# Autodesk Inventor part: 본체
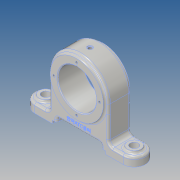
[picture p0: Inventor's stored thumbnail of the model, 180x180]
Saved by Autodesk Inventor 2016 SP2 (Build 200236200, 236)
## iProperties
Created: 2019-05
Part Number: 본체
Material: 알루미늄 6061
Document SubType Name: Modeling
Designer: EZ
Density: 2.7 g/cm^3
Appearance: 알루미늄 - 평지
Mass: 456.014 g
Surface Area: 318.8 cm^2
Volume: 168.894 cm^3
Author: EZ
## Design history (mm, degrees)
sketch "스케치1"
  geometry: L1 (-60, 0)-(60, 0); L2 (-60, -15)-(60, -15); L3 (60, 15)-(-60, 15); A1 r 15 centre (-60, 0) between (-60, 15) and (-60, -15); A2 r 15 centre (60, 0) between (60, -15) and (60, 15); 2 further points
  constraints: 8 end point, 4 point on circle, 4 tangent, 2 centre point, 1 coincident, 1 horizontal, 1 midpoint, 1 parallel
  dimensions: "d0" = 150 dimension on A2 A1; "d1" = 120 distance of L3.start L3.end
extrude "돌출1" new body sketch "스케치1" distance "d2" = 12; taper "d3" = 0 deg
sketch "스케치2"
  geometry: L1 (0, 0)-(0, 60); L2 (0, 0)-(0, 100); L3 (-40, 60)-(-40, 0); L4 (40, 60)-(40, 0); L5 (-40, 0)-(40, 0); L6 (60, 0)-(-60, 0) reference; A1 r 40 centre (0, 60) between (0, 100) and (-40, 60)
  constraints: 10 end point, 4 vertical, 3 point on circle, 1 centre point, 1 coincident, 1 collinear, 1 tangent
  dimensions: "d4" = 60 distance of L1.start L1.end; "d6" = 100 distance of L1.start L2.end
extrude "돌출2" join sketch "스케치2" stored distance "d7" = 30; taper "d8" = 0 deg
sketch "스케치3"
  geometry: L1 (-60, 0)-(60, 0) reference; C1 r 36 at (0, 60); 1 further point
  constraints: 1 centre point
  dimensions: "d9" = 72 diameter of C1; "d10" = 60 distance from line of L1 C1.centre
extrude "돌출3" join sketch "스케치3" stored distance "d11" = 36; taper "d12" = 0 deg
sketch "스케치4"
  geometry: C1 r 36 at (0, 0) reference; C2 r 26 at (0, 0); 1 further point
  constraints: 1 centre point, 1 coincident
  dimensions: "d13" = 52 diameter of C2
extrude "돌출4" cut sketch "스케치4" stored distance "d14" = 36; taper "d15" = 0 deg
sketch "스케치5" dims "d16" = 62
  geometry: L1 (0, 0)-(0, 31); C1 r 36 at (0, 0) reference; 1 further point
  constraints: 2 end point, 1 coincident, 1 vertical, 1 vertical alignment, 2 other
hole "구멍1" sketch "스케치5" at (0, 31) diameter "d17" = 3.242; stored, may be unused: countersink angle "d21" = 90 deg, drill point angle "d23" = 118 deg; dims "d18" = 6, "d19" = 4, "d20" = 2, "d22" = 8
sketch "스케치6"
  geometry: C1 r 9 at (60, 0); A1 r 15 centre (60, 0) between (60, -15) and (60, 15) reference; 1 further point
  constraints: 1 centre point, 1 coincident
  dimensions: "d27" = 18 diameter of C1
extrude "돌출5" join sketch "스케치6" distance "d28" = 3; taper "d29" = 0 deg
sketch "스케치7"
  geometry: C1 r 9 at (0, 0) reference; C2 r 5.5 at (0, 0); 1 further point
  constraints: 1 centre point, 1 coincident
  dimensions: "d30" = 11 diameter of C2
extrude "돌출6" cut sketch "스케치7" stored distance "d31" = 0; taper "d32" = 0 deg
node "작업 평면1"
sketch "스케치8"
  geometry: C1 r 1 at (0, 0); 1 further point
  constraints: 1 centre point, 1 coincident
  dimensions: "d34" = 2 diameter of C1
extrude "돌출7" cut sketch "스케치8" stored distance "d35" = 3; taper "d36" = 0 deg
sketch "스케치9"
  geometry: 1 further point
hole "구멍2" sketch "스케치9" at (0, 0) diameter "d37" = 4.917; stored, may be unused: countersink angle "d41" = 90 deg, drill point angle "d43" = 118 deg; dims "d38" = 12, "d39" = 7, "d40" = 1, "d42" = 10
fillet "모깎기1" dims "d44" = 3
fillet "모깎기3" dims "d46" = 3
chamfer "모따기1" distance "d49" = 1; stored, may be unused: second distance "d50" = 2, angle "d51" = 45 deg
sketch "스케치11"
  geometry: L1 (24, -4)-(96, -4); L2 (96, -4)-(96, 4); L3 (96, 4)-(24, 4); L4 (24, 4)-(24, -4); L5 (24, -4)-(96, 4); L6 (96, -4)-(24, 4); L7 (0, 0)-(120, 0) reference; 1 further point
  constraints: 12 end point, 2 midpoint, 2 parallel, 1 horizontal, 1 perpendicular
  dimensions: "d52" = 72 distance of L1.start L1.end; "d56" = 4 distance from line of L7 L3.end
extrude "돌출8" cut sketch "스케치11" stored distance "d54" = 0; taper "d55" = 0 deg
sketch "스케치12"
  geometry: L1 (60, 60)-(36, 60) reference; L2 (-30, 50)-(30, 50); L3 (30, 50)-(30, 70); L4 (30, 70)-(-30, 70); L5 (-30, 70)-(-30, 50); L6 (-30, 50)-(30, 70); L7 (30, 50)-(-30, 70); 1 further point
  constraints: 12 end point, 2 midpoint, 2 parallel, 1 horizontal, 1 perpendicular
  dimensions: "d57" = 60 distance of L2.start L2.end; "d58" = 10 distance between parallel lines of L1 L4
extrude "돌출9" cut sketch "스케치12" stored distance "d59" = 0; taper "d60" = 0 deg
fillet "모깎기7" dims "d66" = 3, "d67" = 6
fillet "모깎기8" dims "d68" = 3
sketch "스케치14"
  geometry: L1 (-63, 10)-(-9, 10) reference; 2 further points
  constraints: 1 vertical alignment, 1 other
  dimensions: "d69" = 7 distance from line of L1 point (-36, 17)
feature "엠보싱2" sketch "스케치14" dims "d0" = 150, "d1" = 120, "d9" = 72, "d70" = 0.5, "d71" = 0
sketch "스케치15"
  geometry: C1 r 1.5 at (0, 26); 2 further points
  constraints: 1 centre point, 1 vertical alignment, 1 other
  dimensions: "d72" = 3 diameter of C1
extrude "돌출10" cut sketch "스케치15" stored distance "d73" = 0; taper "d74" = 0 deg
node "솔리드1"
pattern_circular "원형 패턴1" dims angle "d25" = 360 deg
mirror "대칭1"
mirror "대칭2"
mirror "대칭3"
